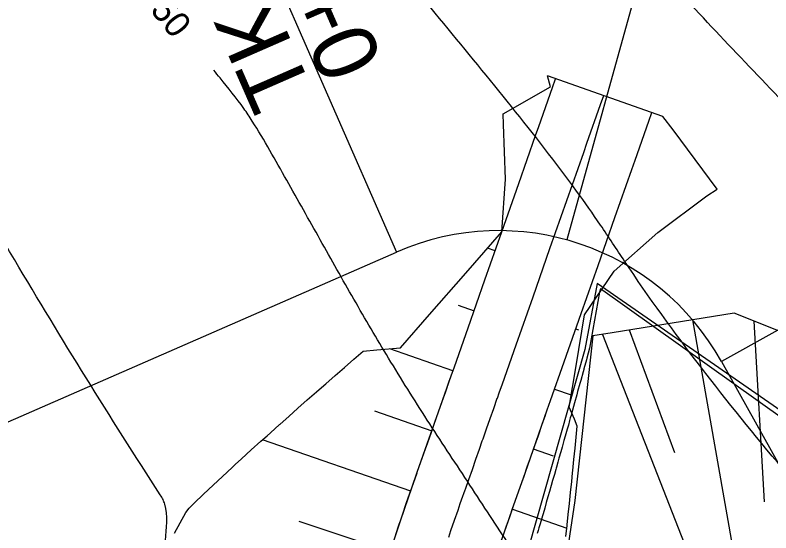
# Model space of a CAD drawing. Extents: x -564037 to -563827, y -1163561 to -1163412.
# Drawn here: x -563935.17 to -563920.35, y -1163476.4 to -1163466.24 of the extents above; entities that cross this region are included whole.
import ezdxf

# ---------------------------------------------------------------- set-up
doc = ezdxf.new("R2010")
doc.units = 0
for name, color, linetype in [('5', 7, 'Continuous'), ('_popis staničení RT1', 7, 'Continuous'), ('Default', 7, 'Continuous'), ('Line', 7, 'Continuous'), ('Vrstva 24', 7, 'Continuous'), ('Vrstva 25', 7, 'Continuous'), ('Vrstva 26', 7, 'Continuous')]:
    doc.layers.add(name, color=color, linetype=linetype)

msp = doc.modelspace()

# ---------------------------------------------------------------- linework, layer by layer
for points in [[(-563924.676, -1163467.645), (-563924.732, -1163467.431)], [(-563924.676, -1163467.645), (-563924.732, -1163467.431)], [(-563924.008, -1163472.119), (-563923.43, -1163471.262), (-563922.574, -1163470.503), (-563921.61, -1163469.782), (-563921.407, -1163469.65), (-563922.274, -1163468.488), (-563922.471, -1163468.226), (-563924.732, -1163467.431)], [(-563927.712, -1163476.432), (-563927.643, -1163476.229), (-563927.62, -1163476.16), (-563927.574, -1163476.026), (-563927.504, -1163475.823), (-563927.434, -1163475.621), (-563927.388, -1163475.491), (-563927.363, -1163475.419), (-563927.293, -1163475.22), (-563927.289, -1163475.206), (-563927.223, -1163475.02), (-563927.153, -1163474.82), (-563927.083, -1163474.621), (-563927.013, -1163474.421), (-563926.957, -1163474.263), (-563926.943, -1163474.222), (-563926.872, -1163474.022), (-563926.802, -1163473.822), (-563926.732, -1163473.623), (-563926.662, -1163473.423), (-563926.662, -1163473.422), (-563926.626, -1163473.319), (-563926.562, -1163473.139), (-563926.294, -1163472.376), (-563925.963, -1163471.432), (-563925.631, -1163470.489), (-563925.3, -1163469.545), (-563924.968, -1163468.602), (-563924.905, -1163468.421), (-563924.637, -1163467.658), (-563924.576, -1163467.486)], [(-563927.712, -1163476.432), (-563927.643, -1163476.229), (-563927.62, -1163476.16), (-563927.574, -1163476.026), (-563927.504, -1163475.823), (-563927.434, -1163475.621), (-563927.388, -1163475.491), (-563927.363, -1163475.419), (-563927.293, -1163475.22), (-563927.289, -1163475.206), (-563927.223, -1163475.02), (-563927.153, -1163474.82), (-563927.083, -1163474.621), (-563927.013, -1163474.421), (-563926.957, -1163474.263), (-563926.943, -1163474.222), (-563926.872, -1163474.022), (-563926.802, -1163473.822), (-563926.732, -1163473.623), (-563926.662, -1163473.423), (-563926.662, -1163473.422), (-563926.626, -1163473.319), (-563926.562, -1163473.139), (-563926.294, -1163472.376), (-563925.963, -1163471.432), (-563925.631, -1163470.489), (-563925.3, -1163469.545), (-563924.968, -1163468.602), (-563924.905, -1163468.421), (-563924.637, -1163467.658), (-563924.576, -1163467.486)], [(-563925.631, -1163470.489), (-563925.556, -1163469.455), (-563925.595, -1163468.382), (-563925.604, -1163468.176), (-563924.676, -1163467.645)], [(-563925.631, -1163470.489), (-563925.556, -1163469.455), (-563925.595, -1163468.382), (-563925.604, -1163468.176), (-563924.676, -1163467.645)], [(-563926.673, -1163476.482), (-563926.628, -1163476.35), (-563926.559, -1163476.15), (-563926.49, -1163475.95), (-563926.445, -1163475.822), (-563926.42, -1163475.751), (-563926.35, -1163475.551), (-563926.345, -1163475.538), (-563926.28, -1163475.351), (-563926.209, -1163475.152), (-563926.139, -1163474.952), (-563926.069, -1163474.753), (-563926.014, -1163474.594), (-563925.999, -1163474.553), (-563925.929, -1163474.353), (-563925.859, -1163474.154), (-563925.789, -1163473.954), (-563925.719, -1163473.755), (-563925.718, -1163473.753), (-563925.682, -1163473.651), (-563925.619, -1163473.47), (-563925.351, -1163472.707), (-563925.019, -1163471.764), (-563924.688, -1163470.82), (-563924.356, -1163469.877), (-563924.025, -1163468.933), (-563923.962, -1163468.753), (-563923.694, -1163467.99), (-563923.633, -1163467.817)], [(-563925.614, -1163476.477), (-563925.546, -1163476.28), (-563925.502, -1163476.154), (-563925.476, -1163476.082), (-563925.406, -1163475.882), (-563925.402, -1163475.869), (-563925.336, -1163475.683), (-563925.266, -1163475.483), (-563925.196, -1163475.284), (-563925.126, -1163475.084), (-563925.07, -1163474.926), (-563925.056, -1163474.884), (-563924.986, -1163474.685), (-563924.915, -1163474.485), (-563924.845, -1163474.286), (-563924.775, -1163474.086), (-563924.775, -1163474.084), (-563924.739, -1163473.982), (-563924.675, -1163473.801), (-563924.407, -1163473.039), (-563924.076, -1163472.095), (-563923.744, -1163471.152), (-563923.413, -1163470.208), (-563923.082, -1163469.265), (-563923.018, -1163469.084), (-563922.75, -1163468.321), (-563922.689, -1163468.149)], [(-563925.614, -1163476.477), (-563925.546, -1163476.28), (-563925.502, -1163476.154), (-563925.476, -1163476.082), (-563925.406, -1163475.882), (-563925.402, -1163475.869), (-563925.336, -1163475.683), (-563925.266, -1163475.483), (-563925.196, -1163475.284), (-563925.126, -1163475.084), (-563925.07, -1163474.926), (-563925.056, -1163474.884), (-563924.986, -1163474.685), (-563924.915, -1163474.485), (-563924.845, -1163474.286), (-563924.775, -1163474.086), (-563924.775, -1163474.084), (-563924.739, -1163473.982), (-563924.675, -1163473.801), (-563924.407, -1163473.039), (-563924.076, -1163472.095), (-563923.744, -1163471.152), (-563923.413, -1163470.208), (-563923.082, -1163469.265), (-563923.018, -1163469.084), (-563922.75, -1163468.321), (-563922.689, -1163468.149)], [(-563924.008, -1163472.119), (-563923.43, -1163471.262), (-563922.574, -1163470.503), (-563921.61, -1163469.782), (-563921.407, -1163469.65), (-563922.274, -1163468.488), (-563922.471, -1163468.226)], [(-563932.051, -1163476.402), (-563931.941, -1163476.2), (-563931.829, -1163475.999), (-563931.764, -1163475.913), (-563931.734, -1163475.884), (-563931.663, -1163475.815), (-563931.479, -1163475.639), (-563931.294, -1163475.463), (-563931.108, -1163475.289), (-563930.921, -1163475.115), (-563930.858, -1163475.056), (-563930.734, -1163474.942), (-563930.546, -1163474.77), (-563930.357, -1163474.6), (-563930.235, -1163474.491), (-563930.17, -1163474.433), (-563929.99, -1163474.272), (-563929.978, -1163474.262), (-563929.809, -1163474.111), (-563929.629, -1163473.951), (-563929.447, -1163473.79), (-563929.265, -1163473.63), (-563929.121, -1163473.503), (-563929.083, -1163473.47), (-563928.9, -1163473.31), (-563928.717, -1163473.15), (-563928.533, -1163472.99), (-563928.348, -1163472.831), (-563928.347, -1163472.83), (-563928.083, -1163472.807), (-563927.618, -1163472.768), (-563927.046, -1163472.112), (-563926.339, -1163471.3), (-563925.631, -1163470.489)], [(-563923.696, -1163471.61), (-563923.713, -1163471.675), (-563923.91, -1163472.772), (-563923.964, -1163472.971), (-563923.973, -1163473.003), (-563924.021, -1163473.177), (-563924.024, -1163473.19), (-563924.037, -1163473.235), (-563924.084, -1163473.408), (-563924.099, -1163473.463), (-563924.144, -1163473.626), (-563924.162, -1163473.689), (-563924.205, -1163473.844), (-563924.224, -1163473.915), (-563924.265, -1163474.063), (-563924.273, -1163474.091), (-563924.288, -1163474.143), (-563924.302, -1163474.193), (-563924.326, -1163474.281), (-563924.349, -1163474.362), (-563924.387, -1163474.498), (-563924.412, -1163474.584), (-563924.449, -1163474.716), (-563924.474, -1163474.806), (-563924.51, -1163474.934), (-563924.532, -1163475.009), (-563924.56, -1163475.107), (-563924.565, -1163475.127), (-563924.572, -1163475.152), (-563924.6, -1163475.249), (-563924.634, -1163475.369), (-563924.663, -1163475.469), (-563924.697, -1163475.587), (-563924.726, -1163475.69), (-563924.759, -1163475.804), (-563924.79, -1163475.91), (-563924.822, -1163476.021), (-563924.829, -1163476.046), (-563924.853, -1163476.129), (-563924.861, -1163476.154), (-563924.885, -1163476.239), (-563924.903, -1163476.3), (-563924.917, -1163476.348), (-563924.935, -1163476.409)], [(-563912.506, -1163487.699), (-563911.986, -1163484.484), (-563911.574, -1163482.655), (-563911.953, -1163481.832), (-563913.535, -1163479.514), (-563916.332, -1163476.565), (-563917.329, -1163476.066), (-563918.514, -1163475.302), (-563923.696, -1163471.61)], [(-563924.375, -1163476.469), (-563924.352, -1163476.253), (-563924.351, -1163476.238), (-563924.329, -1163476.037), (-563924.306, -1163475.82), (-563924.284, -1163475.604), (-563924.261, -1163475.388), (-563924.244, -1163475.216), (-563924.239, -1163475.171), (-563924.217, -1163474.955), (-563924.196, -1163474.738), (-563924.174, -1163474.521), (-563924.153, -1163474.305), (-563924.153, -1163474.303), (-563924.209, -1163474.168), (-563924.309, -1163473.93), (-563924.174, -1163473.121), (-563924.008, -1163472.119)], [(-563924.375, -1163476.469), (-563924.352, -1163476.253), (-563924.351, -1163476.238), (-563924.329, -1163476.037), (-563924.306, -1163475.82), (-563924.284, -1163475.604), (-563924.261, -1163475.388), (-563924.244, -1163475.216), (-563924.239, -1163475.171), (-563924.217, -1163474.955), (-563924.196, -1163474.738), (-563924.174, -1163474.521), (-563924.153, -1163474.305), (-563924.153, -1163474.303), (-563924.209, -1163474.168), (-563924.309, -1163473.93), (-563924.174, -1163473.121), (-563924.008, -1163472.119)], [(-563927.94, -1163477.121), (-563927.62, -1163476.16), (-563927.388, -1163475.491), (-563927.289, -1163475.206), (-563927.055, -1163474.541), (-563926.957, -1163474.263), (-563926.626, -1163473.319), (-563926.562, -1163473.139)], [(-563925.727, -1163476.805), (-563925.502, -1163476.154), (-563925.402, -1163475.869), (-563925.168, -1163475.204), (-563925.07, -1163474.926), (-563924.739, -1163473.982), (-563924.675, -1163473.801)]]:
    msp.add_lwpolyline(points)
msp.add_lwpolyline([(-563930.469, -1163501.126), (-563927.863, -1163499.14), (-563925.937, -1163497.674), (-563921.059, -1163495.43), (-563912.613, -1163489.681), (-563911.421, -1163482.517), (-563913.266, -1163479.715), (-563914.137, -1163478.749), (-563916.309, -1163476.467), (-563917.281, -1163475.995), (-563923.761, -1163471.506), (-563924, -1163472.797), (-563925.435, -1163477.844), (-563927.008, -1163483.992), (-563927.659, -1163487.507), (-563928.13, -1163490.05), (-563928.806, -1163493.379), (-563930.34, -1163499.841), (-563930.622, -1163501.15)], close=True)
at = {"layer": '5'}
for p, q in [((-563952.243, -1163481.627), (-563927.696, -1163470.887)), ((-563921.324, -1163473.035), (-563903.913, -1163504.291))]:
    msp.add_line(p, q, dxfattribs=at)
msp.add_arc((-563925.692, -1163475.468), 5, 29.1194, 113.6313, dxfattribs=at)
at = {"layer": '_popis staničení RT1'}
for points in [[(-563918.577, -1163449.815), (-563924.355, -1163470.65)], [(-563931.752, -1163461.618), (-563927.696, -1163470.887)], [(-563912.207, -1163467.956), (-563921.324, -1163473.035)]]:
    msp.add_lwpolyline(points, dxfattribs=at)
at = {"layer": 'Default'}
msp.add_lwpolyline([(-563917.567, -1163473.488), (-563921.074, -1163472.087), (-563923.466, -1163472.472), (-563923.844, -1163472.533), (-563924.198, -1163475.76), (-563924.511, -1163477.861), (-563924.518, -1163477.902), (-563924.828, -1163479.981), (-563924.849, -1163480.121), (-563924.856, -1163480.165), (-563924.906, -1163480.403), (-563924.984, -1163480.77), (-563924.987, -1163480.784), (-563925.501, -1163483.223), (-563925.543, -1163483.419), (-563925.776, -1163484.521), (-563925.948, -1163485.244), (-563926.867, -1163489.1)], dxfattribs=at)
at = {"layer": 'Line'}
for p, q in [((-563925.762, -1163470.86), (-563925.91, -1163470.808)), ((-563926.485, -1163471.931), (-563926.176, -1163472.039)), ((-563921.893, -1163472.219), (-563920.362, -1163480.924)), ((-563920.479, -1163475.786), (-563920.684, -1163472.243)), ((-563924.122, -1163472.418), (-563924.182, -1163472.397)), ((-563922.236, -1163474.829), (-563923.127, -1163472.417)), ((-563923.655, -1163472.502), (-563920.364, -1163480.938)), ((-563926.59, -1163473.219), (-563927.824, -1163472.785)), ((-563924.596, -1163473.576), (-563924.269, -1163473.691)), ((-563928.125, -1163474.005), (-563927.004, -1163474.398)), ((-563927.417, -1163475.578), (-563930.327, -1163474.573)), ((-563924.618, -1163474.893), (-563925.01, -1163474.756)), ((-563925.424, -1163475.935), (-563924.358, -1163476.306)), ((-563929.614, -1163476.166), (-563927.821, -1163476.761))]:
    msp.add_line(p, q, dxfattribs=at)
at = {"layer": 'Vrstva 24'}
for points in [[(-563919.378, -1163476.01), (-563920.124, -1163475.135), (-563923.224, -1163471.065), (-563923.696, -1163470.358), (-563924.164, -1163469.694), (-563926.769, -1163466.405), (-563928.095, -1163464.779), (-563929.404, -1163463.14), (-563932.31, -1163459.338), (-563933.826, -1163457.042), (-563935.107, -1163454.848), (-563938.341, -1163449.378), (-563939.751, -1163446.922), (-563941.145, -1163444.457), (-563942.639, -1163441.761)], [(-563941.26, -1163493.011), (-563939.004, -1163490.701), (-563935.168, -1163486.585), (-563933.596, -1163484.774), (-563933.04, -1163483.789), (-563932.447, -1163481.939), (-563932.386, -1163481.578), (-563932.335, -1163479.091), (-563932.359, -1163478.881), (-563932.37, -1163478.699), (-563932.356, -1163477.982), (-563932.286, -1163477.265), (-563932.226, -1163476.548), (-563932.242, -1163475.831), (-563932.273, -1163475.745), (-563932.328, -1163475.651), (-563935.188, -1163471.035), (-563938.348, -1163465.934), (-563938.454, -1163465.786), (-563938.858, -1163465.285), (-563944.231, -1163458.582)]]:
    msp.add_spline(points, degree=3, dxfattribs=at)
at = {"layer": 'Vrstva 26'}
for points in [[(-563903.213, -1163473.112), (-563903.335, -1163473.037), (-563904.668, -1163472.172), (-563906.499, -1163470.852), (-563910.711, -1163467.339), (-563913.027, -1163465.278), (-563914.752, -1163463.594), (-563917.784, -1163460.234), (-563919.818, -1163457.596), (-563921.06, -1163455.802), (-563922.391, -1163453.664), (-563923.256, -1163452.127), (-563925.571, -1163447.916), (-563926.722, -1163445.846), (-563927.87, -1163443.819), (-563929.217, -1163441.493)], [(-563905.617, -1163487.172), (-563905.709, -1163486.429), (-563906.139, -1163484.405), (-563906.329, -1163483.595), (-563906.621, -1163482.767), (-563906.829, -1163482.378), (-563907.081, -1163482.014), (-563907.56, -1163481.452), (-563908.067, -1163480.924), (-563908.726, -1163480.275), (-563912.103, -1163476.606), (-563915.337, -1163473.082), (-563915.91, -1163472.421), (-563916.763, -1163471.467), (-563918.06, -1163470.074), (-563919.378, -1163468.702), (-563920.698, -1163467.331), (-563922.003, -1163465.944), (-563924.219, -1163463.46), (-563925.291, -1163462.186), (-563926.342, -1163460.894), (-563927.353, -1163459.538), (-563928.172, -1163458.338), (-563930.361, -1163454.824), (-563930.463, -1163454.637)], [(-563938.486, -1163500.528), (-563938.463, -1163500.513), (-563937.665, -1163500.022), (-563936.97, -1163499.566), (-563930.777, -1163494.949), (-563928.884, -1163493.45), (-563928.656, -1163493.192), (-563928.195, -1163492.447), (-563924.372, -1163485.735), (-563923.788, -1163484.5), (-563923.604, -1163483.639), (-563923.611, -1163481.604), (-563923.712, -1163481.017), (-563924.518, -1163478.475), (-563924.689, -1163477.919), (-563924.751, -1163477.798), (-563925.518, -1163476.583), (-563926.306, -1163475.384), (-563927.092, -1163474.184), (-563927.851, -1163472.968), (-563928.532, -1163471.813), (-563929.192, -1163470.645), (-563929.849, -1163469.476), (-563930.525, -1163468.317), (-563930.688, -1163468.07), (-563931.156, -1163467.471), (-563931.276, -1163467.321)]]:
    msp.add_spline(points, degree=3, dxfattribs=at)

# ---------------------------------------------------------------- texts
at = {"layer": '_popis staničení RT1'}
for s, p in [('0+075.09', (-563927.944, -1163467.147)), ('TK ', (-563929.318, -1163467.748))]:
    msp.add_text(s, height=1.25, rotation=113.6313, dxfattribs=at).set_placement(p)
at = {"layer": 'Vrstva 25'}
msp.add_text('327.50', height=0.5, rotation=308.6467, dxfattribs=at).set_placement((-563933.352, -1163465.125))

doc.saveas('drawing.dxf')
